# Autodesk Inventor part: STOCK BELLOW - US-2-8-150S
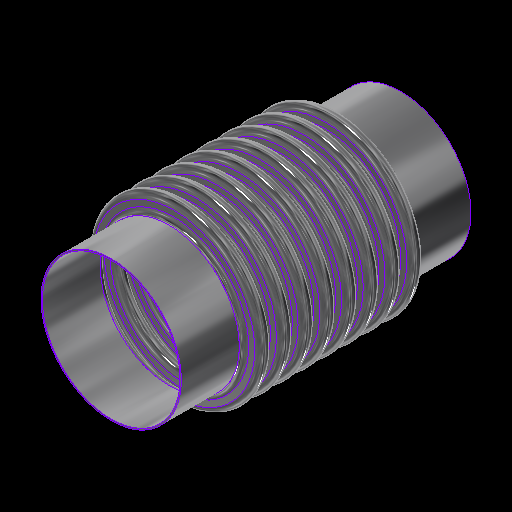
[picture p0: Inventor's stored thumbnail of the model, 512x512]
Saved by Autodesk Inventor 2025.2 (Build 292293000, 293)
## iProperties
Category: 24 GA (0.024 THICK)
RuleStatus: InUse
Created: 2024-01
Part Number: STOCK BELLOW - US-2-8-150S
Project: =STOCK BELLOWS: <Stock Number><SFILL>
Material: ASTM A240-304
Description: =STOCK BELLOWS: <Stock Number>, <SID_> I.D., <SOD_> O.D., <SPLY_> PLY, <Category>, <SNET_CONS> CONS.<PITCH_><STANGENT_> TANGENT<SFILL>
Document SubType Name: Sheet Metal
Designer: GS
Stock Number: U.S-2-8-150S
Surface Area: 890.924 cm^2
Volume: 26.942 cm^3
Sheet Metal Rule: Default
Appearance: STAINLESS STEEL
Mass: 217.079 g
Density: 8.05729 g/cm^3
THK: 0.036
ID: 3.500
OD: 4.250
CONS_: 2
PITCH: 0.500
TANGENT: 0.500
BELLOWS_UPSET: 0.000
d79: 1.000
d82: 1.000
d83: 26.000
d84: 24.000
d174: 8
d214: 8
STHK_: 0.024
SID_: 2.375
SOD_: 3.000
SPITCH_: 0.375
STANGENT__: 1.000
SBELLOWS_UPSET_: 0.000
SDIFF_TAN: 1.000
d252: 2
d275: 2
d287: 0.050
d289: 0.500
d290: 0.000
SOD_NECK: 2 7/16
PLY: 1
PSET: 4.178
PBAR: 1.035
COUNTER: 1.500
NET_TUBE: 3.071
CONS: 2
S_CONS: 0
NET_CONS: 2
ID_M: 88.90 mm
OD_M: 107.95 mm
THK_M: 0.91 mm
ID_U: 3.500 in
OD_U: 4.250 in
THK_U: 0.036 in
TANGENT2: 0.500
TAN_TO_TAN: 1.000 in
d80: 2.571
d81: 10
SID: 2.375
SCONS_: 8
SPITCH: 0.250
STANGENT_: 1.000
SBELLOWS_UPSET: 0.000
SNET_CONS: 8
SS_CONS: 0
SCONS: 8
d190: 8
d191: 1
d192: 1
d193: 8
d194: 0
SIZE: 2.00
PRESSURE: 150
d230: 8
STANGENT: 4.000
SPLY_: 1
d233: 8
d234: 0
d263: 2
d265: 1
d268: 2
d269: 0
d286: 2
d288: 1
d291: 2
d292: 0
SREROLL: 0.750
BLETP: 0.000 ul
PRES_Copy: 85
MATTABLE: 20 GA (0.036 THICK)
PART_NUMBER: U.S-2-8-150S
PITCH_: =, <SPITCH_> PITCH,
CFILL: .
SFILL: .
MESH: ,
COMP: 0.34
EXT: 0.17
LAT: 0.12
ANG: 573
ASR: 2911
LSR: 3153
ANSR: 41
PRES: 150
COMPM: 3.4
EXTM: 1.7
LATM: 1.20
ASRM: 509.803
PRESM: 10.342
LSRM: 552.185
ANSRM: 7.18
TEMPMIN: 20
TEMPMAX: 800
TEMPMINM: -7
TEMPMAXM: 427
WEIGHTM: 0.165
WEIGHT: 0.363
Author: GS
Keywords: 20 GA (0.036 THICK)
Comments: =STOCK BELLOW - <STOCK NUMBER>
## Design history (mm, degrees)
sketch "Sketch2"
  geometry: L1 (0, -177.245)-(0, 562.856) reference; L2 (45.364, 0)-(44.45, 0); L3 (48.082, -2.718)-(50.343, -2.718); L4 (48.082, -3.632)-(50.343, -3.632); L5 (50.343, -9.982)-(48.082, -9.982); L6 (50.343, -9.068)-(48.082, -9.068); L7 (45.364, -12.7)-(44.45, -12.7); L8 (48.082, 0)-(48.082, -12.7); L9 (50.343, -6.35)-(53.975, -6.35); L10 (44.45, 0)-(44.45, -12.7); L11 (20.376, 102.841)-(20.376, 101.926); L12 (58.262, 457.127)-(58.262, 349.177); L13 (58.262, 444.427)-(58.262, 336.477); L14 (93.133, -58.817)-(93.133, -71.517); L15 (118.746, -66.401)-(118.746, -66.401); L16 (50.343, -9.068)-(50.343, -9.982); L17 (48.082, -9.068)-(48.082, -9.982); L18 (48.082, -9.525)-(50.343, -9.525); L19 (53.975, 0)-(53.975, -12.7); L20 (-50.343, -9.068)-(-50.343, -9.982); L21 (-50.343, -2.718)-(-48.082, -2.718); L22 (-50.343, -3.632)-(-48.082, -3.632); L23 (-48.082, -9.068)-(-50.343, -9.068); L24 (-50.343, -9.525)-(-48.082, -9.525); L25 (-48.082, -9.982)-(-50.343, -9.982); L26 (-48.082, -9.068)-(-48.082, -9.982); L27 (-44.45, 0.653)-(-44.45, -12.047); L28 (-48.082, -6.35)-(-44.45, -6.35); L29 (-50.343, 0.653)-(-50.343, -12.7); L30 (-53.061, 0)-(-53.975, 0); L31 (-53.975, 0)-(-53.975, -12.7); L32 (-53.061, -12.7)-(-53.975, -12.7); A1 r 2.718 centre (48.082, 0) between (45.364, 0) and (48.082, -2.718); A2 r 3.632 centre (48.082, 0) between (44.45, 0) and (48.082, -3.632); A3 r 3.632 centre (50.343, -6.35) between (50.343, -9.982) and (50.343, -2.718); A4 r 2.718 centre (50.343, -6.35) between (50.343, -9.068) and (50.343, -3.632); A5 r 2.718 centre (48.082, -12.7) between (48.082, -9.982) and (45.364, -12.7); A6 r 3.632 centre (48.082, -12.7) between (48.082, -9.068) and (44.45, -12.7); A7 r 3.175 centre (50.343, -6.35) between (50.343, -9.525) and (53.518, -6.35); A8 r 3.175 centre (48.082, -12.7) between (48.082, -9.525) and (44.907, -12.7); A9 r 2.718 centre (-50.343, -12.7) between (-50.343, -9.982) and (-53.061, -12.7); A10 r 2.718 centre (-48.082, -6.35) between (-48.082, -9.068) and (-48.082, -3.632); A11 r 3.175 centre (-48.082, -6.35) between (-48.082, -9.525) and (-44.907, -6.35); A12 r 3.632 centre (-48.082, -6.35) between (-48.082, -9.982) and (-48.082, -2.718); A13 r 3.175 centre (-50.343, -12.7) between (-50.343, -9.525) and (-53.518, -12.7); A14 r 3.632 centre (-50.343, -12.7) between (-50.343, -9.068) and (-53.975, -12.7); A15 r 2.718 centre (-50.343, 0) between (-53.061, 0) and (-50.343, -2.718); A16 r 3.632 centre (-50.343, 0) between (-53.975, 0) and (-50.343, -3.632); 10 further points
  constraints: 62 end point, 38 point on circle, 20 tangent, 16 centre point, 12 parallel, 9 midpoint, 7 vertical, 6 coincident, 6 concentric, 6 point on line, 4 equal radius, 4 perpendicular, 3 horizontal, 1 collinear, 1 horizontal alignment, 10 other
  dimensions: "THK" = 0.9144 distance of L11.start L11.end; "ID" = 88.9 distance of L11.end point (20.376, 13.026); "OD" = 107.95 distance of L12.start L12.end; "PITCH" = 12.7 distance of L12.start L13.start; "TANGENT" = 12.7 distance of L14.start L14.end; "BELLOWS_UPSET" = 0 distance of L15.start L15.end; "d43" = 88.9 diameter of L10 L1 (= ID); "d44" = 107.95 diameter of L9.end L1 (= OD); "d45" = 0.9144 distance between parallel lines of L5 L6 (computed from THK, PLY); "d46" = 3.6322 radius of A3 (computed from PITCH, THK, PLY); "UPSET_PITCH" = 12.7 distance of L2.end L7.end (derived); "SIDEWALL_ANGLE" = 360 deg dimension on L3 L9 (derived); "CON_GAP" = 5.4356 distance of point (48.082, -9.068) point (48.082, -3.632) (derived); "TAN1" = 4.98728 dimension on A8 (derived); "TAN2" = 4.98728 dimension on A7 (derived); "LEG1" = 2.2606 distance of L18.start L18.end (derived); "d278" = 0.9144 distance between parallel lines of L25 L23 (derived); "d279" = 3.6322 radius of A12 (derived); "d280" = 12.7 distance of L30.end L31.end (derived); "d281" = 360 deg dimension on L21 L28 (derived); "d282" = 5.4356 distance of point (-50.343, -9.068) point (-50.343, -3.632) (derived); "d283" = 4.98728 dimension on A13 (derived); "d284" = 4.98728 dimension on A11 (derived); "d285" = 2.2606 distance of L24.start L24.end (derived); "d293" = 88.9 diameter of L27 L1 (derived); "d294" = 107.95 diameter of L31 L1 (derived)
  node "Sketch Rectangular Pattern1" dims "d31" = 25.4, "ID" = 88.9
  node "Sketch Rectangular Pattern2" dims "d39" = 25.4, "PITCH" = 12.7
revolve "CONS" stored, may be unused: angle "d48" = 90 deg
node "BELLOW MIDPLANE"
pattern_linear "Rectangular Pattern2" dims "d52" = 12.7 (= UPSET_PITCH)
sketch "Sketch5"
  geometry: C1 r 45.364 at (0, 0) reference; C2 r 44.45 at (0, 0) reference
extrude "TANGENT" new body sketch "Sketch5" distance "d53" = 12.7 (= TANGENT); taper "d54" = 0 deg
revolve "SAMETAN" stored, may be unused: angle "d65" = 90 deg
revolve "DIFFTAN" stored, may be unused: angle "d70" = 90 deg
sketch "Sketch9"
  geometry: L1 (53.319, 0)-(-53.319, 0) reference; L2 (0, -17.78)-(0, 17.78) reference; L3 (38.085, 0)-(-38.085, 0); L4 (38.085, -11.906)-(38.085, 11.906); L5 (25.385, -11.906)-(25.385, 11.906); L6 (13.15, 11.906)-(13.15, -11.906); L7 (-25.385, -11.906)-(-25.385, 11.906); L8 (-38.085, -11.906)-(-38.085, 11.906); L9 (37.291, -11.906)-(37.291, 11.906); L10 (38.085, -11.906)-(37.291, -11.906); L11 (38.085, 11.906)-(37.291, 11.906); L12 (13.546, 11.906)-(12.753, 11.906); L13 (12.753, 11.906)-(12.753, -11.906); L14 (12.753, -11.906)-(13.546, -11.906); L15 (13.546, -11.906)-(13.546, 11.906); L16 (-13.546, 11.906)-(-13.546, -11.906); L17 (-13.15, 11.906)-(-13.15, -11.906); L18 (-13.546, -11.906)-(-12.753, -11.906); L19 (-12.753, -11.906)-(-12.753, 11.906); L20 (-12.753, 11.906)-(-13.546, 11.906); L21 (-38.085, -11.906)-(-37.291, -11.906); L22 (-37.291, -11.906)-(-37.291, 11.906); L23 (-37.291, 11.906)-(-38.085, 11.906); L24 (-38.085, 11.906)-(-38.085, -11.906); L25 (38.085, -0.397)-(-38.085, -0.397); L26 (-38.085, -0.397)-(-38.085, 0.397); L27 (-38.085, 0.397)-(38.085, 0.397); L28 (38.085, 0.397)-(38.085, -0.397); L29 (-38.085, 11.906)-(38.085, 11.906); L30 (38.085, 11.906)-(38.085, 12.7); L31 (38.085, 12.7)-(-38.085, 12.7); L32 (-38.085, 12.7)-(-38.085, 11.906); L33 (38.085, -11.906)-(-38.085, -11.906); L34 (-38.085, -11.906)-(-38.085, -12.7); L35 (-38.085, -12.7)-(38.085, -12.7); L36 (38.085, -12.7)-(38.085, -11.906); 30 further points
  constraints: 68 end point, 13 midpoint, 13 parallel, 8 horizontal, 7 perpendicular, 6 equal length, 3 point on line, 2 vertical, 14 other
  dimensions: "d115" = 23.8125 distance of L4.start L4.end (derived); "d116" = 12.7 distance between parallel lines of L4 L5 (derived); "d117" = 12.23516 distance between parallel lines of L5 L6 (derived); "d125" = 38.53427 distance between parallel lines of L7 L6 (derived); "d127" = 12.7 distance between parallel lines of L8 L7 (derived); "d128" = 24.93516 distance between parallel lines of L6 L4 (derived); "d130" = 76.16943 distance between parallel lines of L8 L4 (derived); "RULER_THK" = 0.79375 distance between parallel lines of L4 L9; "d135" = 0.79375 distance of L13.end L14.end (derived); "d138" = 26.29911 distance of L13.end L16.end (derived); "d143" = 0.79375 distance of L22.end L8.end (derived); "d144" = 0.79375 distance between parallel lines of L27 L25 (derived)
extrude "RULER" join sketch "Sketch9" distance "d149" = 0.79375 (derived); taper "d150" = 0 deg
extrude "BARS" join sketch "Sketch9" distance "d151" = 0.79375 (derived); taper "d152" = 0 deg
pattern_linear "Rectangular Pattern4" dims "d155" = 26.29911 (derived)
sketch "Sketch13"
  geometry: L1 (93.149, -52.467)-(93.149, -77.867); L2 (30.772, 0)-(30.162, 0); L3 (30.772, -9.525)-(30.162, -9.525); L4 (35.414, -7.449)-(32.849, -7.449); L5 (35.414, -6.839)-(32.849, -6.839); L6 (35.414, -4.763)-(38.1, -4.762); L7 (32.849, -2.076)-(35.414, -2.076); L8 (32.849, 0)-(32.849, -9.525); L9 (30.162, 0)-(30.162, -9.525); L10 (58.254, -420.231)-(58.254, -496.431); L11 (58.254, -429.756)-(58.254, -505.956); L12 (58.254, -448.806)-(58.254, -525.006); L13 (58.254, -458.331)-(58.254, -534.531); L14 (58.254, -467.856)-(58.254, -544.056); L15 (58.254, -477.381)-(58.254, -553.581); L16 (58.254, -486.906)-(58.254, -563.106); L17 (58.254, -439.281)-(58.254, -515.481); L18 (20.376, 102.536)-(20.376, 101.926); L19 (32.849, -2.686)-(35.414, -2.686); L20 (0, -696.204)-(0, 235.481) reference; L21 (-23.752, 0)-(142.514, 0) reference; A1 r 2.076 centre (32.849, 0) between (30.772, 0) and (32.849, -2.076); A2 r 2.076 centre (32.849, -9.525) between (32.849, -7.449) and (30.772, -9.525); A3 r 2.686 centre (32.849, -9.525) between (32.849, -6.839) and (30.162, -9.525); A4 r 2.076 centre (35.414, -4.763) between (35.414, -6.839) and (35.414, -2.686); A5 r 2.686 centre (35.414, -4.763) between (35.414, -7.449) and (35.414, -2.076); A6 r 2.686 centre (32.849, 0) between (30.162, 0) and (32.849, -2.686); 6 further points; 1 other entity
  constraints: 38 end point, 15 point on circle, 9 tangent, 6 centre point, 6 parallel, 5 vertical alignment, 4 point on line, 4 vertical, 3 coincident, 3 concentric, 2 collinear, 2 equal radius, 1 horizontal, 1 perpendicular, 23 other
  dimensions: "SBELLOWS_UPSET_" = 0 distance of point (118.762, -66.401) point (118.762, -66.401); "STOTAL_THK_BELLOW__" = 0.6096 distance between parallel lines of L4 L5 (derived); "d224" = 2.68605 radius of A5 (derived); "d225" = 9.525 distance of L2.end L3.end (derived); "SSIDEWALL_ANGLE_" = 0 deg angle of L7 L6 (derived); "SSCON_GAP_" = 4.1529 distance of point (32.849, -6.839) point (32.849, -2.686) (derived); "d235" = 60.325 diameter of L9 L20 (derived); "d236" = 76.2 diameter of L6.end L20 (derived)
  node "Sketch Rectangular Pattern4" dims "d228" = 25.4
  node "Sketch Rectangular Pattern5" dims "d229" = 25.4
revolve "SBELLOW" stored, may be unused: angle "d197" = 90 deg
pattern_linear "Rectangular Pattern5" dims "d204" = 9.525 (derived)
revolve "STANGENT" stored, may be unused: angle "d240" = 90 deg
revolve "SSAMETAN" stored, may be unused: angle "d241" = 90 deg
revolve "SDIFFTAN" stored, may be unused: angle "d246" = 90 deg
revolve "INVCON" stored, may be unused: angle "d295" = 90 deg
pattern_linear "Rectangular Pattern6" dims "d298" = 12.7 (derived)
revolve "INVTANGENT" stored, may be unused: angle "d302" = 90 deg
revolve "INVSAMETAN" stored, may be unused: angle "d307" = 90 deg
revolve "INVDIFFTAN" stored, may be unused: angle "d312" = 90 deg
sketch "ID BELLOW MOUNT CALC"
  geometry: L1 (44.45, 0)-(38.1, 0); L2 (38.1, 0)-(38.1, 12.7); L3 (38.1, 12.7)-(44.45, 12.7); L4 (44.45, 12.7)-(44.45, 0); L5 (36.513, 12.7)-(35.598, 12.7); L6 (35.598, 12.7)-(35.598, 0); L7 (35.598, 0)-(36.513, 0); L8 (36.513, 0)-(36.513, 12.7); L9 (0, -2.54)-(0, 15.24) reference; L10 (-8.89, 0)-(53.34, 0) reference; 1 further point
  constraints: 16 end point, 5 parallel, 2 collinear, 2 horizontal, 2 perpendicular
  dimensions: "d314" = 12.7 distance of L5.end L6.end (derived); "d315" = 0.9144 distance of L5.start L5.end (derived); "IG" = 1.5875 distance between parallel lines of L2 L8; "PIPE_OD" = 88.9 diameter of L4 L9; "PIPE_WALL" = 6.35 distance of L2.end L3.end; "ID_MT_BELLOW" = 71.1962 diameter of L6 L9 (derived)
revolve "CFILL" stored, may be unused: angle "d320" = 90 deg
pattern_linear "Rectangular Pattern7" dims "d323" = 12.7 (derived)
revolve "SFILL" stored, may be unused: angle "d324" = 90 deg
pattern_linear "Rectangular Pattern8" dims "d327" = 9.525 (derived)
node "STOCK BELLOW MIDPLANE"
node "BELLOW"
sketch "Sketch6"
  geometry: L1 (-12.7, 45.364)-(0, 45.364); L2 (0, 45.364)-(0, 44.45); L3 (0, 44.45)-(-12.7, 44.45); L4 (-12.7, 44.45)-(-12.7, 45.364); L5 (10.16, 0)-(-60.96, 0) reference; L6 (-38.1, -89.422)-(-38.1, 153.44) reference; 1 further point
  constraints: 8 end point, 2 parallel, 1 horizontal, 1 perpendicular
  dimensions: "d61" = 12.7 distance of L2.end L3.end (derived); "d62" = 0.9144 distance of L1.end L2.end (derived); "d63" = 88.9 diameter of L3 L5 (derived); "d64" = 25.4 distance between parallel lines of L4 L6 (derived)
sketch "Sketch12"
  geometry: 1 further point
sketch "Sketch14"
  geometry: L1 (-25.4, 30.772)-(0, 30.772); L2 (0, 30.772)-(0, 30.162); L3 (0, 30.162)-(-25.4, 30.162); L4 (-25.4, 30.162)-(-25.4, 30.772); L5 (5.08, 0)-(-30.48, 0) reference; L6 (0, -8.89)-(0, 53.34) reference; 1 further point
  constraints: 8 end point, 2 parallel, 1 collinear, 1 horizontal, 1 perpendicular
  dimensions: "d237" = 0.6096 distance of L3.end L1.start (derived); "d238" = 60.325 diameter of L3 L5 (derived); "d239" = 25.4 distance of L1.start L1.end (derived); "SOD_NECK" = 61.5442 diameter of L1 L5 (derived)
sketch "Sketch15"
  geometry: L1 (-8.89, 0)-(53.34, 0) reference; L2 (30.163, -76.2)-(30.772, -76.2); L3 (30.772, -76.2)-(30.772, -101.6); L4 (30.772, -101.6)-(30.163, -101.6); L5 (30.163, -101.6)-(30.163, -76.2); L6 (0, -124.46)-(0, 35.56) reference; 1 further point
  constraints: 8 end point, 2 parallel, 1 horizontal, 1 perpendicular
  dimensions: "d205" = 25.4 distance of L4.end L2.start (derived); "d206" = 0.6096 distance of L3.end L4.end (derived); "d207" = 60.325 diameter of L5 L6 (derived); "d208" = 76.2 distance between parallel lines of L1 L2 (derived)
node "TANGENT_"
node "SAME_TAN"
sketch "Sketch8"
  geometry: L1 (45.364, -25.4)-(44.45, -25.4); L2 (44.45, -25.4)-(44.45, -38.1); L3 (44.45, -38.1)-(45.364, -38.1); L4 (45.364, -38.1)-(45.364, -25.4); L5 (0, -48.26)-(0, 22.86) reference; L6 (-89.422, 0)-(153.44, 0) reference; 1 further point
  constraints: 8 end point, 2 parallel, 1 horizontal, 1 perpendicular
  dimensions: "d66" = 88.9 diameter of L2 L5 (derived); "TOTAL_THK_BELLOW" = 0.9144 distance of L2.end L3.end (derived); "d68" = 25.4 distance between parallel lines of L1 L6 (derived); "d69" = 12.7 distance of L1.end L2.end (derived)
node "DIFF_TAN"
node "Sketch Rectangular Pattern3" dims "d138" = 26.29911 (derived), "d141" = 25.4
node "SBELLOW_"
node "STANGENT_"
node "SSAME_TAN"
sketch "Sketch16"
  geometry: L1 (30.772, -76.2)-(30.163, -76.2); L2 (30.163, -76.2)-(30.163, -101.6); L3 (30.163, -101.6)-(30.772, -101.6); L4 (30.772, -101.6)-(30.772, -76.2); L5 (0, -124.46)-(0, 35.56) reference; L6 (-8.89, 0)-(53.34, 0) reference; 1 further point
  constraints: 8 end point, 2 parallel, 1 horizontal, 1 perpendicular
  dimensions: "SDIFF_TAN" = 25.4 distance of L3.end L1.start; "d243" = 0.6096 distance of L2.end L3.end (derived); "d244" = 76.2 distance between parallel lines of L1 L6 (derived); "d245" = 60.325 diameter of L2 L5 (derived)
node "SDIFF_TAN"
body "Solid15"
sketch "Sketch17"
  geometry: L1 (53.975, 12.7)-(53.061, 12.7); L2 (53.061, 12.7)-(53.061, 0); L3 (53.061, 0)-(53.975, 0); L4 (53.975, 0)-(53.975, 12.7); L5 (0, -2.54)-(0, 15.24) reference; L6 (-10.795, 0)-(64.77, 0) reference; 2 further points
  constraints: 8 end point, 2 parallel, 1 horizontal, 1 midpoint, 1 perpendicular, 1 point on line
  dimensions: "INVTANGENT" = 12.7 distance of L3.end L1.start (derived); "d300" = 0.9144 distance of L1.start L1.end (derived); "d301" = 107.95 diameter of L4 L5 (derived)
body "Solid16"
sketch "Sketch18"
  geometry: L1 (53.975, -25.4)-(53.061, -25.4); L2 (53.061, -25.4)-(53.061, -38.1); L3 (53.061, -38.1)-(53.975, -38.1); L4 (53.975, -38.1)-(53.975, -25.4); L5 (-10.795, 0)-(64.77, 0) reference; L6 (0, -48.26)-(0, 22.86) reference; 1 further point
  constraints: 8 end point, 2 parallel, 1 horizontal, 1 perpendicular
  dimensions: "d303" = 25.4 distance between parallel lines of L1 L5 (derived); "d304" = 12.7 distance of L3.end L1.start (derived); "d305" = 0.9144 distance of L2.end L3.end (derived); "d306" = 107.95 diameter of L4 L6 (derived)
body "Solid17"
sketch "Sketch19"
  geometry: L1 (53.975, -25.4)-(53.061, -25.4); L2 (53.061, -25.4)-(53.061, -38.1); L3 (53.061, -38.1)-(53.975, -38.1); L4 (53.975, -38.1)-(53.975, -25.4); L5 (0, -48.26)-(0, 22.86) reference; L6 (-10.795, 0)-(64.77, 0) reference; 1 further point
  constraints: 8 end point, 2 parallel, 1 horizontal, 1 perpendicular
  dimensions: "d308" = 12.7 distance of L1.end L2.end (derived); "d309" = 107.95 diameter of L4 L5 (derived); "d310" = 0.9144 distance of L2.end L3.end (derived); "d311" = 25.4 distance between parallel lines of L1 L6 (derived)
body "Solid18"
body "Solid19"
body "Solid20"
other parameters: "BMPL" = -38.1, "PSET" = 106.1212 (computed from OD, THK, PLY) [user parameter], "PBAR" = 26.29911 (= 0.570796 x PITCH + OD - ID) [user parameter; used in 1 equation term], "COUNTER" = 15 [user parameter], "NET_TUBE" = 77.99823 (computed from CONS_, PBAR, TANGENT) [user parameter], "S_CONS" = 0 [user parameter; used in 1 equation term], "ID_M" = 88.9 (= ID) [user parameter], "OD_M" = 107.95 (= OD) [user parameter], "THK_M" = 0.9144 (= THK) [user parameter], "ID_U" = 88.9 (= ID) [user parameter], "OD_U" = 107.95 (= OD) [user parameter], "THK_U" = 0.9144 (= THK) [user parameter], "D_UNITS" = 0 [user parameter], "TANGENT2" = 12.7 [user parameter], "TAN_TO_TAN" = 25.4 [user parameter], "OD_NECK" = 90.7288 [user parameter], "d79" = 25.4, "d80" = 65.29823 [user parameter], "d82" = 25.4, "d83" = 660.4, "d84" = 609.6, "sa_0" = 4, "FRAME_THK" = 0.79375 [user parameter], "CON_FLAT" = 12.23516 [user parameter], "SID" = 60.325 [user parameter], "SPITCH" = 6.35 [user parameter], "STANGENT_" = 25.4 [user parameter], "SBELLOWS_UPSET" = 0 [user parameter], "SS_CONS" = 0 [user parameter], "STAN_TO_TAN_" = 76.2 [user parameter], "d100" = 0.6096 [user parameter], "d191" = 25.4 [user parameter], "d194" = 0 [user parameter], "STANGENT" = 101.6 [user parameter], "d234" = 0 [user parameter], "SUPSET_PITCH_" = 9.525 [user parameter], "d269" = 0 [user parameter], "d287" = 1.27, "d289" = 12.7, "d290" = 0, "d292" = 0 [user parameter], "Thickness" = 3.048 (derived), "KFactor" = 4.4, "BendRadius" = 3.048 (derived), "BendReliefWidth" = 3.048 (derived), "BendReliefDepth" = 1.524 (derived), "CornerReliefSize" = 12.192 (derived), "SeamGap" = 0.00508, "MinimumRemnant" = 6.096 (derived), "TransitionRadius" = 3.048 (derived), "JacobiRadiusSize" = 3.048 (derived), "GapSize" = 3.048 (derived), "SREROLL" = 19.05 [user parameter], "CUR_STK_PITCH" = 9.525 [user parameter], "d328" = -38.1 (derived), "ASR" = 29110 [user parameter], "LSR" = 31530 [user parameter], "BLETP" = 0 [user parameter], "ASRM" = 5098.0343 [user parameter], "PRESM" = 103.41975 [user parameter], "LSRM" = 5521.8489 [user parameter], "ANSRM" = 71.8033 [user parameter], "TEMPMIN" = 2664.83333 [user parameter], "TEMPMAX" = 6998.16667 [user parameter], "TEMPMINM" = 2664.83333 [user parameter], "TEMPMAXM" = 6998.16667 [user parameter], "WEIGHT" = 1.64646 [user parameter], "WEIGHTM" = 0.00165 [user parameter]
